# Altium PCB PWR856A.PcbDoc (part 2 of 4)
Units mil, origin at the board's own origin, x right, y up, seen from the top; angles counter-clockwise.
Board outline 4000 x 4000 mil, 8 copper layers (Top Layer, Signal Layer 1, Signal Layer 2, Signal Layer 3, Signal Layer 4, Signal Layer 5, Signal Layer 6, Bottom Layer), stack 60.4 mil thick; 246 components, 78 nets, 563 pads, 817 vias.
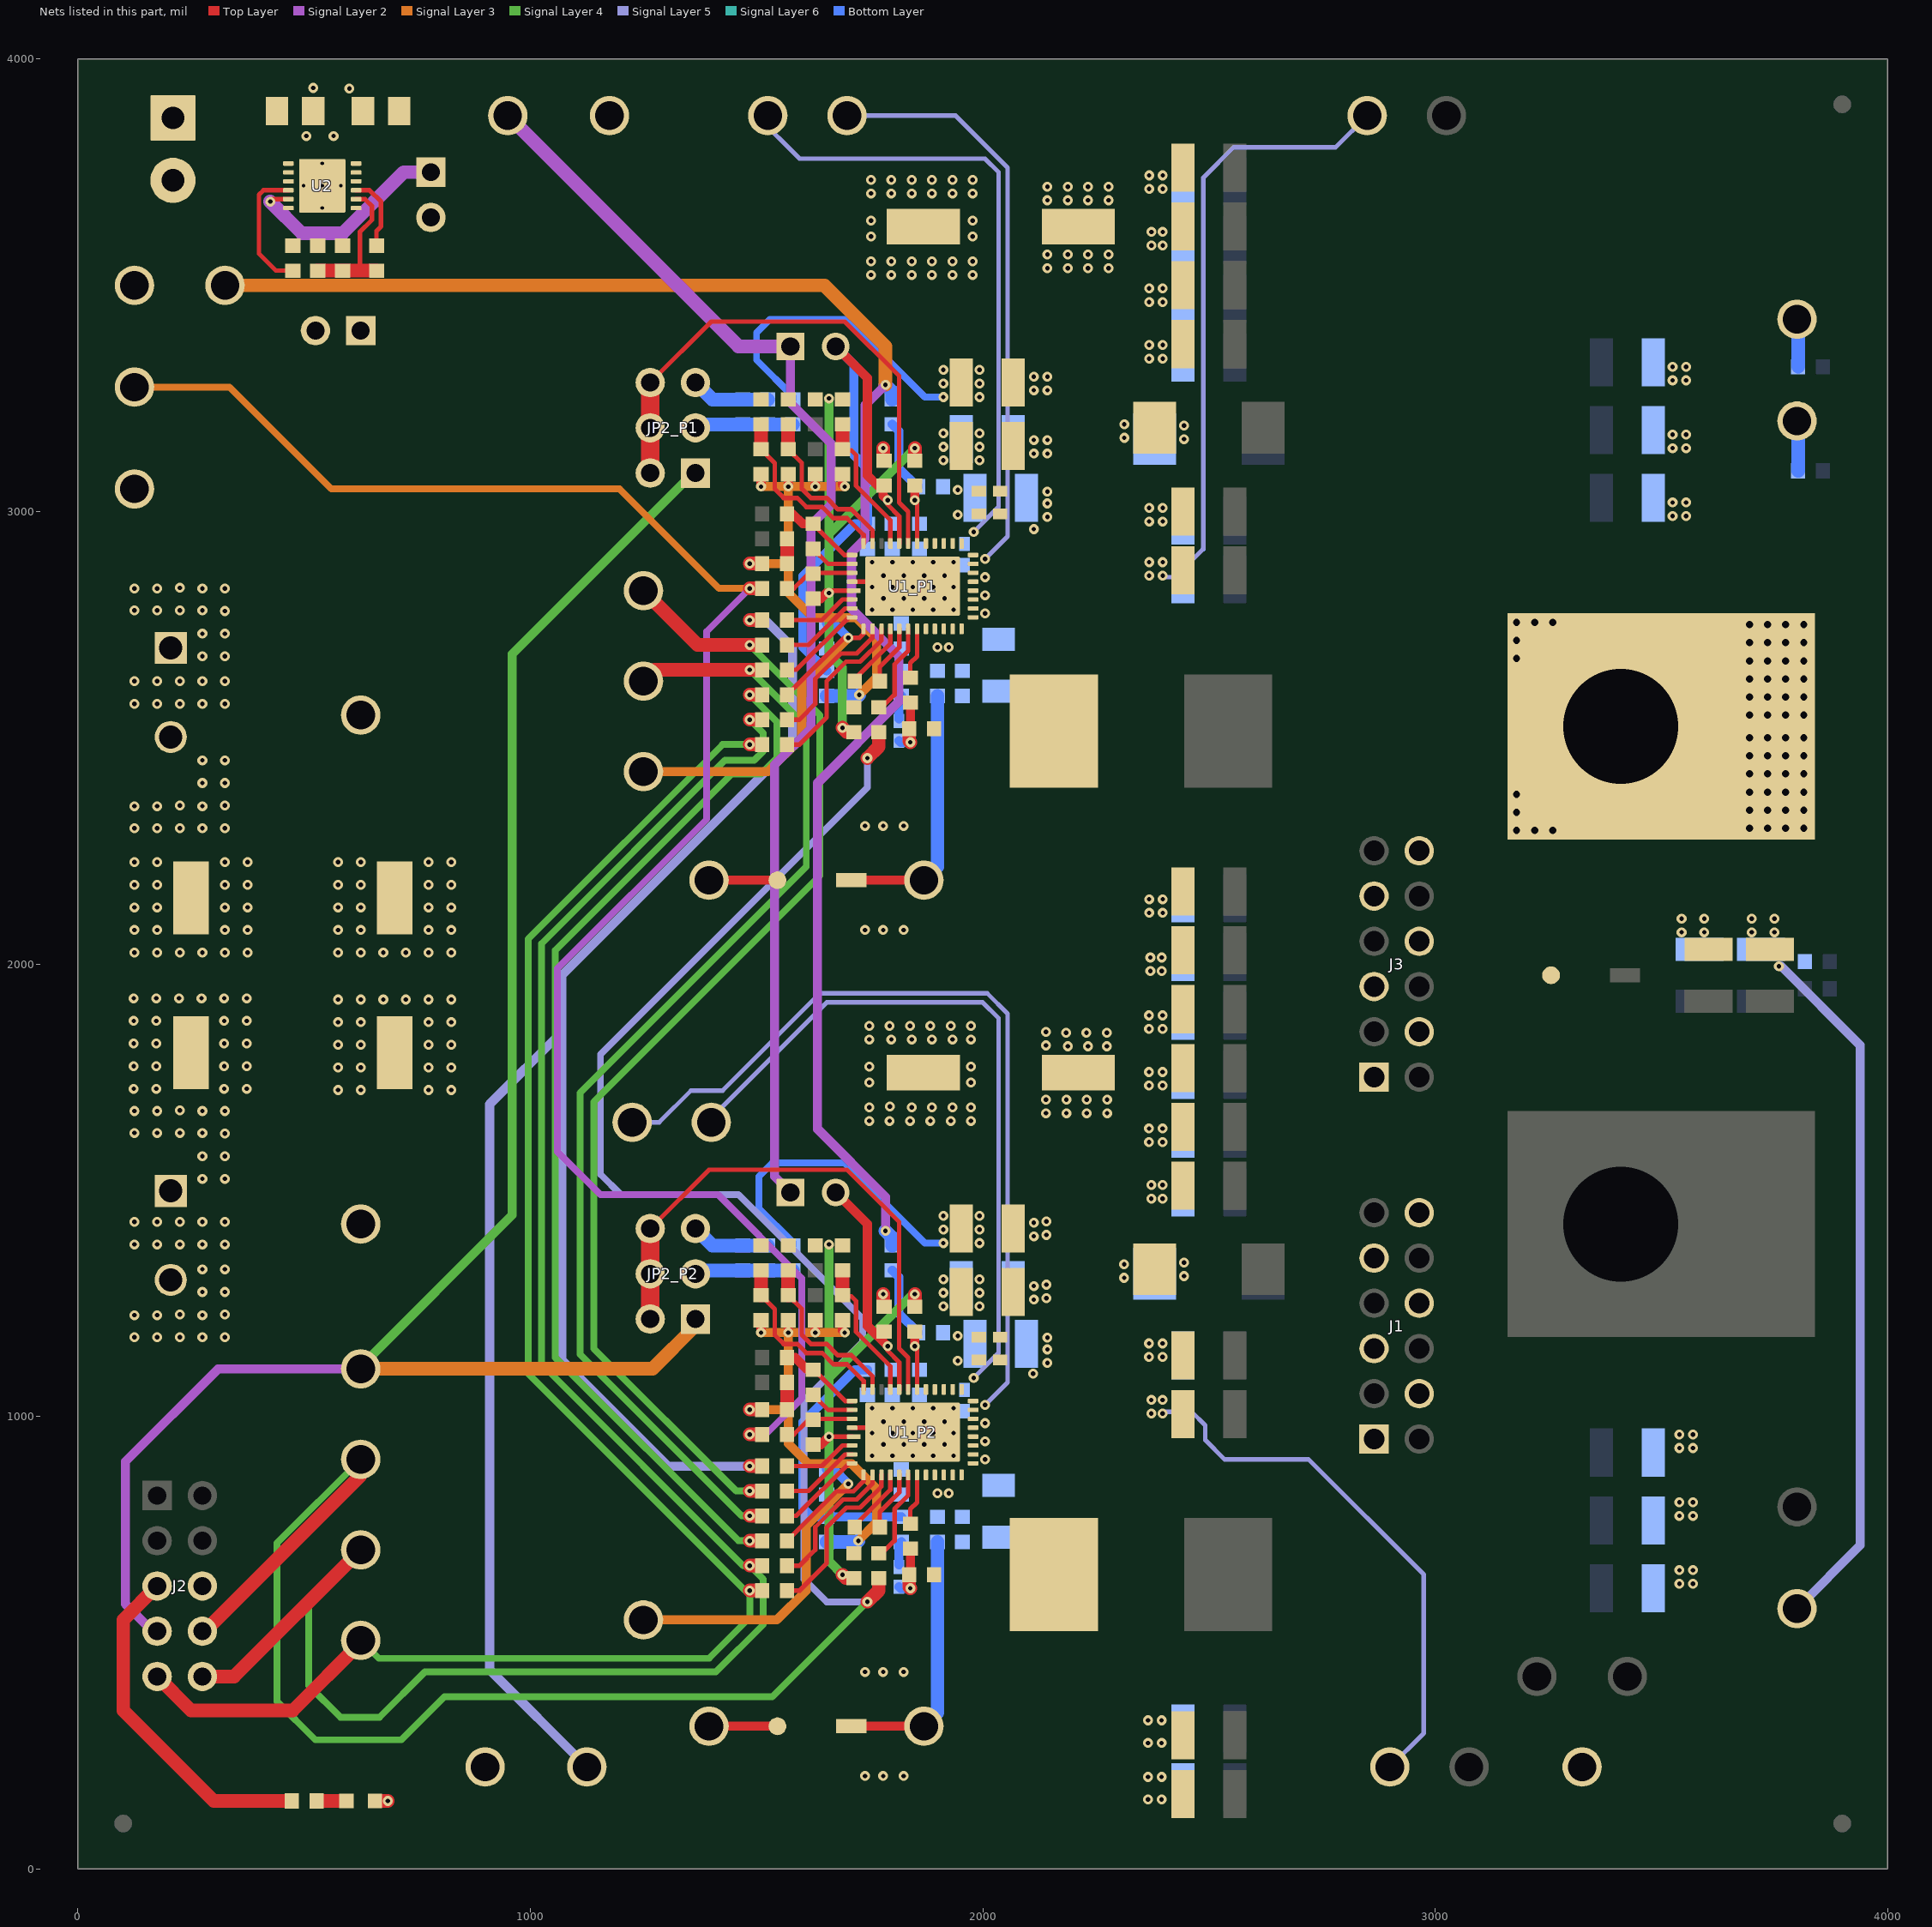
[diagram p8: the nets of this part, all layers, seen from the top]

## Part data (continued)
C47 C48 C63 C64: library part CMP-0012642-3, "CAP, Tantalum Polymer, 470 uF, 6.3 V, +/- 20%, 0.01 ohm, 7343-40 SMD", Cap_Case=D4, Manufacturer=Panasonic, PartNumber=6TPF470MAH, Supplier Part Number 1=P16636CT-ND, Tolerance_%=20%, Value1="0.01 ohm", Value2=6.3V, ValueDisplayed=470uF
D1_P1 D1_P2: library part CMP-0028846-2, "Diode, Schottky, 30 V, 0.5 A, SOD-523", Manufacturer="Torex USA Corporation", PartNumber=XBS053V15R-G, Supplier Part Number 1=XBS053V15R-G-ND, Value1=0.5A, Value2=0.47V
FID1 FID2 FID3 FID4 FID5 FID6: library part CMP-0077181-1, "Fiducial mark.  There is nothing to buy or mount.", Manufacturer=N/A
H3 H4 H5 H6: library part CMP-0003620-1, "Bumpon, Hemisphere, 0.44 X 0.20, Clear", Manufacturer=3M, PartNumber="SJ-5303 (CLEAR)", Supplier Part Number 1=SJ5303-7-ND
J1 J3: library part CMP-0055669-1, "Receptacle, 2.54mm, 6x2, Gold, TH", Color=Black, Current_A=5.7A, Manufacturer=Samtec, PartNumber=SSW-106-23-F-D, Voltage_V=550V
J2: library part CMP-0054834-1, "Header (shrouded), 100mil, 5x2, Gold, TH", Manufacturer="TE Connectivity", PartNumber=5103308-1, Supplier Part Number 1=A33159-ND
JP1_P1 JP1_P2: library part CMP-0054576-1, "Header, 2.54 mm, 2x1, Gold, TH", Manufacturer="Sullins Connector Solutions", PartNumber=GBC02SAAN
JP2_P1 JP2_P2: library part CMP-0054565-1, "Header, 100mil, 3x2, Gold, TH", Color=Black, Current_A=3A, Manufacturer="Sullins Connector Solutions", PartNumber=PBC03DAAN, Supplier Part Number 1=S2011E-03-ND, Voltage_V=1.8kV
JP3 JP4: library part CMP-0054952-1, "Header, 100mil, 2x1, Tin, TH", Manufacturer="TE Connectivity", PartNumber=5-146278-2, Supplier Part Number 1=5-146278-2-ND
L1 L2: library part CMP-0060889-1, "Inductor, Shielded, Ferrite, 300 nH, 52 A, 0.00015 ohm, SMD", Manufacturer=Coilcraft, PartNumber=SLC1480-301MLB, Value1="0.00015 ohm", Value2=52A, ValueDisplayed=300nH
LBL1: library part CMP-0003625-1, "Thermal Transfer Printable Labels, 0.650\" W x 0.200\" H - 10,000 per roll", Manufacturer=Brady, PartNumber=THT-14-423-10, Supplier Part Number 1=97C5133
LED1: library part CMP-0002905-1, "LED, Green, SMD", Color=Green, Manufacturer="Wurth Elektronik", PartNumber=150060GS75000, Supplier Part Number 1=732-4971-1-ND, Value1=W, Value2=3.2V
Logo1: library part CMP-0074837-1, "IEC 61010-1 Hot Surface Warning"
Logo4: library part CMP-0074769-1
Logo5: library part CMP-0074847-1, "FCC_disclaimer"
NT1_P1 NT1_P2: library part CMP-0078142-1, "Single point connection between nets.", Manufacturer=N/A
R1_P1 R1_P2 R2_P1 R2_P2 R4_P1 R4_P2 R15_P1 R15_P2 R16_P1 R16_P2 R17_P1 R17_P2 R19_P1 R19_P2 R22_P1 R22_P2 R23_P1 R23_P2 R24_P1 R24_P2 R25_P1 R25_P2 R27_P1 R27_P2 R32 R33 R37 R39: library part CMP-0025874-3, "RES, 0, 5%, 0.1 W, 0603", Manufacturer=Panasonic, PartNumber=ERJ-3GEY0R00V, Power_W=100mW, Supplier Part Number 1=P0.0GCT-ND, TempCo="600 ppm/C", Tolerance_%=5%, Value2=0.1W, Value_Code=0000, ValueDisplayed=0
R3_P1 R3_P2: library part CMP-0025703-4, "RES, 10, 5%, 0.1 W, AEC-Q200 Grade 0, 0603", Manufacturer=Vishay-Dale, Power_W=100mW, Supplier Part Number 1=541-10GCT-ND, TempCo="200 ppm/C", Tolerance_%=5%, Value2=0.1W, Value_Code=10R0, ValueDisplayed=10
R5_P1 R5_P2 R34 R35 R36 R38: library part CMP-0022448-4, "RES, 49.9, 1%, 0.1 W, AEC-Q200 Grade 0, 0603", Manufacturer=Vishay-Dale, PartNumber=CRCW060349R9FKEA, Power_W=100mW, Supplier Part Number 1=541-49.9HCT-ND, TempCo="100 ppm/C", Tolerance_%=1%, Value2=0.1W, Value_Code=49R9, ValueDisplayed=49.9
R6_P1 R6_P2: library part CMP-0018617-3, "RES, 1.0, 5%, 0.25 W, AEC-Q200 Grade 0, 1206", Manufacturer=Vishay-Dale, PartNumber=CRCW12061R00JNEA, Power_W=250mW, Supplier Part Number 1=541-1.0ECT-ND, TempCo="200 ppm/C", Tolerance_%=5%, Value2=0.25W, Value_Code=1R00, ValueDisplayed=1.0
R7_P1 R7_P2: library part CMP-0023197-3, "RES, 5.11 k, 1%, 0.1 W, 0603", Manufacturer="Yageo America", Power_W=100mW, Supplier Part Number 1=311-5.11KHRCT-ND, TempCo="200 ppm/C", Tolerance_%=1%, Value2=0.1W, Value_Code=5k11, ValueDisplayed=5.11k
R8_P1 R8_P2 R26_P1 R26_P2: library part CMP-0022746-3, "RES, 10.0 k, 1%, 0.1 W, 0603", Manufacturer="Yageo America", PartNumber=RC0603FR-0710KL, Power_W=100mW, Supplier Part Number 1=311-10.0KHRCT-ND, TempCo="200 ppm/C", Tolerance_%=1%, Value2=0.1W, Value_Code=10k0, ValueDisplayed=10.0k
R9_P1 R9_P2: library part CMP-0023018-3, "RES, 30.1 k, 1%, 0.1 W, 0603", Manufacturer="Yageo America", Power_W=100mW, Supplier Part Number 1=311-30.1KHRCT-ND, TempCo="200 ppm/C", Tolerance_%=1%, Value2=0.1W, Value_Code=30k1, ValueDisplayed=30.1k
R10_P1 R10_P2 R11_P1 R11_P2 R12_P1 R12_P2 R18_P1 R18_P2 R20_P1 R20_P2: library part CMP-0022000-4, "RES, 10.5 k, 1%, 0.1 W, AEC-Q200 Grade 0, 0603", Manufacturer=Vishay-Dale, PartNumber=CRCW060310K5FKEA, Power_W=100mW, Supplier Part Number 1=541-10.5KHCT-ND, TempCo="100 ppm/C", Tolerance_%=1%, Value2=0.1W, Value_Code=10k5, ValueDisplayed=10.5k
R13_P1 R13_P2: library part CMP-0022490-4, "RES, 53.6 k, 1%, 0.1 W, AEC-Q200 Grade 0, 0603", Manufacturer=Vishay-Dale, PartNumber=CRCW060353K6FKEA, Power_W=100mW, Supplier Part Number 1=541-53.6KHCT-ND, TempCo="100 ppm/C", Tolerance_%=1%, Value2=0.1W, Value_Code=53k6, ValueDisplayed=53.6k
R14_P1 R14_P2: library part CMP-0022708-3, "RES, 7.50 k, 1%, 0.1 W, 0603", Manufacturer=Panasonic, Power_W=100mW, Supplier Part Number 1=P7.50KHCT-ND, TempCo="100 ppm/C", Tolerance_%=1%, Value2=0.1W, Value_Code=7k50, ValueDisplayed=7.50k
R21_P1 R21_P2: library part CMP-0022237-4, "RES, 24.9 k, 1%, 0.1 W, AEC-Q200 Grade 0, 0603", Manufacturer=Vishay-Dale, PartNumber=CRCW060324K9FKEA, Power_W=100mW, Supplier Part Number 1=541-24.9KHCT-ND, TempCo="100 ppm/C", Tolerance_%=1%, Value2=0.1W, Value_Code=24k9, ValueDisplayed=24.9k
R28: library part CMP-0022109-5, "RES, 1.00 k, 1%, 0.1 W, AEC-Q200 Grade 0, 0603", Manufacturer=Vishay-Dale, PartNumber=CRCW06031K00FKEA, Power_W=100mW, Supplier Part Number 1=541-1.00KHCT-ND, TempCo="100 ppm/C", Tolerance_%=1%, Value2=0.1W, Value_Code=1k00, ValueDisplayed=1.00k
R29: library part CMP-0022439-4, "RES, 47.5 k, 1%, 0.1 W, AEC-Q200 Grade 0, 0603", Manufacturer=Vishay-Dale, PartNumber=CRCW060347K5FKEA, Power_W=100mW, Supplier Part Number 1=541-47.5KHCT-ND, TempCo="100 ppm/C", Tolerance_%=1%, Value2=0.1W, Value_Code=47k5, ValueDisplayed=47.5k
R30: library part CMP-0022066-4, "RES, 15.0 k, 1%, 0.1 W, AEC-Q200 Grade 0, 0603", Manufacturer=Vishay-Dale, PartNumber=CRCW060315K0FKEA, Power_W=100mW, Supplier Part Number 1=541-15.0KHCT-ND, TempCo="100 ppm/C", Tolerance_%=1%, Value2=0.1W, Value_Code=15k0, ValueDisplayed=15.0k
R31: library part CMP-0023182-2, "RES, 560 k, 1%, 0.1 W, 0603", Manufacturer="Yageo America", PartNumber=RC0603FR-07560KL, Power_W=100mW, Supplier Part Number 1=311-560KHRCT-ND, TempCo="200 ppm/C", Tolerance_%=1%, Value2=0.1W, Value_Code=560k
SH-JP1 SH-JP2 SH-JP3 SH-JP4: "Shunt, 100mil, Gold plated, Black", Alternate Manufacturer=Samtec, Alternate PartNumber=SNT-100-BK-G, Manufacturer=3M, Supplier Part Number 1=3M9580-ND
SMB1_P1 SMB1_P2 SMB2: library part CMP-0075106-1, "Connector, Receptacle, 50 ohm, TH", Manufacturer="JAE Electronics", PartNumber=SMBR004D00, Supplier Part Number 1=SMBR004D00-ND
T1 T2: library part CMP-0055506-1, "Terminal Block, 2x1, 5mm, Green, TH", Color=Green, Manufacturer="Phoenix Contact", Supplier Part Number 1=277-6405-ND
T3 T5: library part CMP-0055443-1, "Terminal 90A Lug", Manufacturer=Panduit, Supplier Part Number 1=CB70-14-CY-ND, Voltage_V=600V
T4: library part CMP-0074913-1, "Terminal Block, 3.5mm Pitch, 2x1, TH", Color=Grey, Current_A=6A, Manufacturer="On-Shore Technology", PartNumber=ED555/2DS, Supplier Part Number 1=ED1514-ND, Voltage_V=150V
TP1_P1 TP1_P2 TP6 TP12 TP13 TP19 TP26: library part CMP-0055147-1, "Test Point, Multipurpose, Red, TH", Color=Red, Manufacturer=Keystone, Supplier Part Number 1=36-5010-ND
TP2_P1 TP2_P2 TP5_P1 TP5_P2 TP7 TP8 TP9 TP10 TP17 TP18 TP21 TP27 TP29 TP31: library part CMP-0055149-1, "Test Point, Multipurpose, White, TH", Color=White, Manufacturer=Keystone, Supplier Part Number 1=36-5012-ND
TP3_P1 TP3_P2 TP4_P1 TP4_P2 TP11 TP15 TP16 TP20 TP23 TP24 TP25 TP30 TP32: library part CMP-0055148-1, "Test Point, Multipurpose, Black, TH", Color=Black, Manufacturer=Keystone, Supplier Part Number 1=36-5011-ND
TP14 TP28: library part CMP-0055149-1, "Test Point, Multipurpose, White, TH", Color=White, Manufacturer=Keystone, PartNumber=5012, Supplier Part Number 1=36-5012-ND
TP22: library part CMP-0055147-1, "Test Point, Multipurpose, Red, TH", Color=Red, Manufacturer=Keystone, PartNumber=5010, Supplier Part Number 1=36-5010-ND
U1_P1 U1_P2: library part CMP-0014071-6, "2.95-16V 40A PMBUS Stackable Synchronous Buck Converter, RVF0040A (LQFN-CLIP-40)", Alternate Manufacturer="Texas Instruments", Alternate PartNumber=TPS546D24RVFT
U2: library part CMP-0066007-2, "800-mA Ultra-Low-Noise, High-PSRR LDO, DNT0012B (WSON-12)", Alternate Manufacturer="Texas Instruments", PartNumber=LP38798SD-ADJ/NOPB
ZZ1: library part CMP-0003616-3
ZZ2: library part CMP-0077236-1
ZZ3: library part CMP-0077237-1
ZZ4: library part CMP-0077238-1
ZZ5: library part AssemblyNote, "This Assembly Note will show in the PcbDoc and associated outputs"

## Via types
v1: diameter 22, hole 10, Top Layer to Bottom Layer, tented both sides, 676 vias
v2: diameter 32, hole 16, Top Layer to Bottom Layer, 116 vias
v3: diameter 22, hole 10, Top Layer to Bottom Layer, tented bottom, 20 vias
v4: diameter 19.68, hole 7.87, Top Layer to Bottom Layer, 5 vias

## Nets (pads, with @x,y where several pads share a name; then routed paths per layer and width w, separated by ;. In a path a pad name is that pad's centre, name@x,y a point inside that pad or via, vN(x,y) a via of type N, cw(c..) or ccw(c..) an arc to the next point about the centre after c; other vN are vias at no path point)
ADRSEL_P1: R12_P1.2 R20_P1.1 U1_P1.31 | length 378.2
  Top Layer w10: R12_P1.2@1570,3137.56 1600,3107.56 1600,3050 1620,3030 1655,3030 1680,3005 1710,3005 1756.42,2958.58 U1_P1.31@1756.42,2929.49
  Top Layer w30: R12_P1.2@1570,3137.56 R20_P1.1@1570,3192.44
ADRSEL_P2: R12_P2.2 R20_P2.1 U1_P2.31 | length 378.2
  Top Layer w10: R12_P2.2@1570,1267.56 1600,1237.56 1600,1180 1620,1160 1655,1160 1680,1135 1710,1135 1756.42,1088.58 U1_P2.31@1756.42,1059.49
  Top Layer w30: R12_P2.2@1570,1267.56 R20_P2.1@1570,1322.44
AGND_P1: C11_P1.1 C18_P1.2 C21_P1.2 NT1_P1.1 R18_P1.2 R19_P1.2 R20_P1.2 R21_P1.2 U1_P1.37 | length 1149.7
  Top Layer w10: v1@1662.16,2825.16 U1_P1.37@1711.14,2825.16
  Top Layer w20: C21_P1.2@1625,2807.44 1642.44,2807.44 v1@1655,2820
  Top Layer w30: v1(1690,2522) 1699.56,2512.44 C18_P1.2@1715,2512.44 ; C11_P1.1@1850,3112.56 v1(1850,3140)
  Signal Layer 4 w20: v1(1660,3250) 1660,2950 ; v1(1690,2522) 1690,2655 1660,2685 v1(1660,2820) 1660,2950 ; v1(1850,3140) 1660,2950
AGND_P2: C11_P2.1 C18_P2.2 C21_P2.2 NT1_P2.1 R18_P2.2 R19_P2.2 R20_P2.2 R21_P2.2 U1_P2.37 | length 1148.8
  Top Layer w10: v1@1662.16,955.16 U1_P2.37@1711.14,955.16
  Top Layer w20: C21_P2.2@1625,937.44 1642.44,937.44 v1@1655,950
  Top Layer w30: v1(1690,650) 1697.56,642.44 C18_P2.2@1715,642.44 ; C11_P2.1@1850,1242.56 v1(1850,1270)
  Signal Layer 4 w20: v1(1660,1380) 1660,1085 ; v1(1690,650) 1660,680 v1(1660,955) 1660,1085 ; v1(1850,1270) 1845,1270 1660,1085
AUX_5V: C23.1 JP1_P1.1 JP1_P2.1 TP6.1 U2.10 U2.11 U2.12 | length 2809.8
  Signal Layer 2 w20: JP1_P2.1@1575,1495 1540,1530 1540,2440 1620,2520 1620,2970 1665,3015 1665,3150 1575,3240 JP1_P1.1@1575,3365
  Signal Layer 2 w30: TP6.1@950,3875 1460,3365 JP1_P1.1@1575,3365
AVIN: C22.1 JP4.2 R2_P1.2 R2_P2.2 T4.1 TP19.1 U2.1 U2.2 U2.3 | length 3759.5
  Signal Layer 2 w20: v1(1785,1410) 1785,1485 1635,1635 1635,2400 1815,2580 1815,2680 1710,2785 1710,2909.46 1740,2939.46 1740,3235 v1(1785,3280)
  Signal Layer 3 w30: TP19.1@325,3500 1650,3500 1785,3365 v1(1785,3280)
  Bottom Layer w30: v1(1785,1410) 1800,1395 R2_P2.2@1800,1377.56 ; v1(1785,3280) 1800,3265 R2_P1.2@1800,3247.56
AVIN_P1: C10_P1.2 C11_P1.2 R2_P1.1 R3_P1.1 U1_P1.26 | length 292.6
  Top Layer w10: v1(1850,3025) 1854.84,3020.16 U1_P1.26@1854.84,2929.49
  Top Layer w20: v1(1850,3025) C11_P1.2@1850,3057.44
  Bottom Layer w20: R2_P1.1@1800,3192.44 1815,3177.44 1815,3095 1855,3055 R3_P1.1@1857.44,3055
AVIN_P2: C10_P2.2 C11_P2.2 R2_P2.1 R3_P2.1 U1_P2.26 | length 291.2
  Top Layer w10: v1(1850,1155) 1854.84,1150.16 U1_P2.26@1854.84,1059.49
  Top Layer w20: v1(1850,1155) C11_P2.2@1850,1187.44
  Bottom Layer w20: R2_P2.1@1800,1322.44 1815,1307.44 1815,1227.44 R3_P2.1@1857.44,1185
BP1V5_P1: C18_P1.1 C19_P1.1 R7_P1.2 R8_P1.1 R10_P1.1 R11_P1.1 R12_P1.1 R13_P1.1 U1_P1.4 | length 1237.5
  Top Layer w10: C19_P1.1@1717.44,2630 1795.79,2708.35 U1_P1.4@1795.79,2740.51
  Top Layer w20: v1(1510,3055) R13_P1.1@1510,3082.44 ; v1(1570,3055) R12_P1.1@1570,3082.44 ; v1(1630,3055) R11_P1.1@1630,3082.44 ; R10_P1.1@1690,3082.44 1690,3060 v1(1695,3055)
  Top Layer w30: v1(1485,2885) R8_P1.1@1512.44,2885
  Signal Layer 3 w20: v1(1485,2885) 1570,2885 ; v1(1510,3055) v1(1570,3055) ; v1(1695,3055) v1(1630,3055) v1(1570,3055) ; v1(1727,2595) 1765,2633 1765,2720 1720,2765 1625,2765 1570,2820 1570,2885 ; 1570,2885 v1(1570,3055)
  Bottom Layer w30: R7_P1.2@1655,2592.44 1724.44,2592.44 v1(1727,2595)
BP1V5_P2: C18_P2.1 C19_P2.1 R7_P2.2 R8_P2.1 R10_P2.1 R11_P2.1 R12_P2.1 R13_P2.1 U1_P2.4 | length 1241.3
  Top Layer w10: C19_P2.1@1717.44,755 1717.44,759.44 1795.79,837.79 U1_P2.4@1795.79,870.51
  Top Layer w20: v1(1510,1185) R13_P2.1@1510,1212.44 ; v1(1570,1185) R12_P2.1@1570,1212.44 ; v1(1630,1185) R11_P2.1@1630,1212.44 ; R10_P2.1@1690,1212.44 1690,1190 v1(1695,1185)
  Top Layer w30: v1(1485,1015) R8_P2.1@1512.44,1015
  Signal Layer 3 w20: v1(1485,1015) 1570,1015 ; v1(1510,1185) v1(1570,1185) ; v1(1695,1185) v1(1630,1185) v1(1570,1185) ; v1(1725,725) 1765,765 1765,840 1710,895 1615,895 1570,940 1570,1015 ; 1570,1015 v1(1570,1185)
  Bottom Layer w30: R7_P2.2@1655,722.44 1722.44,722.44 v1(1725,725)
CLK: J2.9 R25_P1.2 R25_P2.2 TP10.1 | length 3893.9
  Top Layer w30: J2.9@175,425 250,350 475,350 625,500 TP10.1@625,505 ; v1(1485,615) R25_P2.2@1512.44,615 ; v1(1485,2485) R25_P1.2@1512.44,2485
  Signal Layer 4 w15: TP10.1@625,505 665,465 1395,465 1485,555 v1(1485,615) 1475,615 995,1095 995,2055 1425,2485 v1(1485,2485)
CNTL: J2.7 JP2_P1.1 JP2_P2.1 TP9.1 | length 4098.6
  Signal Layer 2 w20: J2.7@175,525 165,525 105,585 105,900 310,1105 TP9.1@625,1105
  Signal Layer 4 w20: TP9.1@625,1105 625,1110 960,1445 960,2685 1360,3085 JP2_P1.1@1365,3085
  Signal Layer 3 w30: TP9.1@625,1105 1270,1105 1365,1200 JP2_P2.1@1365,1215
DATA: J2.10 R23_P1.2 R23_P2.2 TP7.1 | length 4452.6
  Top Layer w30: J2.10@275,425 345,425 TP7.1@625,705 ; v1(1485,670) R23_P2.2@1512.44,670 ; v1(1485,2540) R23_P1.2@1512.44,2540
  Signal Layer 4 w15: TP7.1@625,705 510,590 510,405 580,335 666.93,335 766.93,435 1410,435 1515,540 1515,640 v1(1485,670) 1470,670 1025,1115 1025,2045 1430,2450 1495,2450 1515,2470 1515,2510 v1(1485,2540)
DGND_P1: C19_P1.2 U1_P1.5 | length 128.3
  Top Layer w10: C19_P1.2@1772.56,2630 1772.56,2656.56 1815.47,2699.47 U1_P1.5@1815.47,2740.51
DGND_P2: C19_P2.2 U1_P2.5 | length 133.3
  Top Layer w10: C19_P2.2@1772.56,755 1772.56,788.56 1815.47,831.47 U1_P2.5@1815.47,870.51
EN_P1: JP2_P1.2 JP2_P1.4 JP2_P1.6 U1_P1.27 | length 1234.5
  Top Layer w10: JP2_P1.6@1265,3285 1400,3420 1695,3420 1815,3300 1815,3020 1835.16,2999.84 U1_P1.27@1835.16,2929.49
  Top Layer w40: JP2_P1.2@1265,3085 JP2_P1.4@1265,3185 JP2_P1.6@1265,3285
EN_P2: JP2_P2.2 JP2_P2.4 JP2_P2.6 U1_P2.27 | length 1230.3
  Top Layer w10: JP2_P2.6@1265,1415 1395,1545 1700,1545 1815,1430 1815,1150 1835.16,1129.84 U1_P2.27@1835.16,1059.49
  Top Layer w40: JP2_P2.2@1265,1215 JP2_P2.4@1265,1315 JP2_P2.6@1265,1415
EXT_SYNC: R17_P1.1 R17_P2.1 TP27.1 | length 4253.7
  Top Layer w30: v1(1485,890) R17_P2.1@1512.44,890 ; v1(1485,2760) R17_P1.1@1512.44,2760
  Signal Layer 5 w20: TP27.1@1125,225 910,440 910,1690 1070,1850 ; v1(1485,890) 1305,890 1070,1125 1070,1850 ; v1(1485,2760) 1520,2760 1580,2700 1580,2485 1070,1975 1070,1850
GND_P1: C1_P1.1 C1_P2.1 C2_P1.2 C2_P2.2 C3_P1.2 C3_P2.2 C4_P1.2 C4_P2.2 C5_P1.1 C5_P2.1 C6_P1.1 C6_P2.1 C7_P1.1 C7_P2.1 C8_P1.1 C8_P2.1 C9_P1.1 C9_P2.1 C10_P1.1 C10_P2.1 C14_P1.1 C14_P2.1 C15_P1.1 C15_P2.1 C16_P1.1 C16_P2.1 C20_P1.2 C20_P2.2 C22.2 C23.2 C24.2 C25.2 C26.2 C27.2 C28.2 C29.2 C30.2 C31.2 C32.2 C33.2 C34.2 C35.1 C36.1 C37.1 C38.1 C39.1 C40.1 C41.1 C42.1 C43.1 C44.1 C45.1 C46.1 C47.2 C48.2 C49.1 C50.1 C51.1 C52.1 C53.1 C54.1 C55.1 C56.1 C57.1 C58.1 C59.1 C60.1 C61.1 C62.1 C63.2 C64.2 C65.2 C66.2 C67.2 C68.2 C69.2 C70.2 C71.2 C72.2 J1.1 J1.4 J1.5 J1.8 J1.9 J1.12 J2.6 J3.1 J3.4 J3.5 J3.8 J3.9 J3.12 JP2_P1.5 JP2_P2.5 JP3.2 LED1.1 NT1_P1.2 NT1_P2.2 R6_P1.1 R6_P2.1 R14_P1.2 R14_P2.2 R30.1 R31.1 R36.1 SMB1_P1.2 SMB1_P2.2 SMB2.2 T2.1 T2.2 T4.2 T5.1 TP3_P1.1 TP3_P2.1 TP4_P1.1 TP4_P2.1 TP11.1 TP15.1 TP16.1 TP20.1 TP23.1 TP24.1 TP25.1 TP30.1 TP32.1 U1_P1.13 U1_P1.14 U1_P1.15 U1_P1.16 U1_P1.17 U1_P1.18 U1_P1.19 U1_P1.20 U1_P1.36 U1_P1.41@1845,2835 U1_P2.13 U1_P2.14 U1_P2.15 U1_P2.16 U1_P2.17 U1_P2.18 U1_P2.19 U1_P2.20 U1_P2.36 U1_P2.41@1845,965 U2.6 U2.7 U2.13 | length 8256.8
  Top Layer w10: U1_P2.36@1711.14,974.84 1835.16,974.84 U1_P2.41@1845,965 ; U1_P1.36@1711.14,2844.84 1835.16,2844.84 U1_P1.41@1845,2835
  Top Layer w20: TP4_P2.1@1397.48,315 SMB1_P2.2@1546.26,315 ; TP4_P1.1@1397.48,2185 SMB1_P1.2@1546.26,2185
  Top Layer w30: LED1.1@656.5,150 v1(685,150) ; C15_P2.1@1780,1242.56 v1(1780,1270) ; C15_P1.1@1780,3112.56 v1(1780,3140)
  Signal Layer 5 w10: TP3_P2.1@1225,1650 1285,1650 1355,1720 1425,1720 1640,1935 2010,1935 2055,1890 2055,1075 v1(2005,1025) ; TP3_P1.1@1700,3875 1940,3875 2055,3760 2055,2945 v1(2005,2895) ; v1@2400,1010 2462.13,1010 2492,980.13 2492,947.72 2534.8,904.92 2720.08,904.92 2975,650 2975,300 TP30.1@2900,225 ; v1@2400,2855 2425,2855 2486.8,2916.8 ; 2487.81,2916.8 2487.81,3738.09 2554.72,3805 2780,3805 TP16.1@2850,3875
  Signal Layer 5 w20: v1(3760,1995) 3765,1995 3940,1820 3940,715 TP25.1@3800,575
  Signal Layer 6 w10: 2486.8,2916.8 2487.81,2916.8
  Bottom Layer w30: JP2_P2.5@1365,1415 1402.44,1377.56 R14_P2.2@1470,1377.56 C20_P2.2@1525,1377.56 ; JP2_P1.5@1365,3285 1402.44,3247.56 R14_P1.2@1470,3247.56 C20_P1.2@1525,3247.56
  other v1: 2365.4,153 2395.4,153 2365.4,203 2395.4,203 1740,205 1780,205 1825,205 2365.4,278 2395.4,278 2365.4,328 2395.4,328 1740,435 1780,435 1825,435 3540,630 3570,630 3540,660 3570,660 3540,780 3570,780 3540,810 3570,810 2005,905 1845.48,913 1890.48,913 1935.48,913 3540,930 3570,930 1870.48,938 1915.48,938 2005,945 3540,960 3570,960 1845.48,963 1890.48,963 1935.48,963 2005,985 1870.48,988 1915.48,988 2372.59,1006.2 2397.59,1006.2 1845.48,1018 1890.48,1018 1935.48,1018 2372.59,1036.2 2397.59,1036.2 2111.59,1094.2 2142.92,1118 2367.59,1131.2 2397.59,1131.2 2142.92,1148 2367.59,1161.2 2397.59,1161.2 2142.92,1174 125,1175 175,1175 225,1175 275,1175 325,1175 125,1223.62 175,1223.62 275,1223.62 225,1225 325,1225 2112.92,1258 2140.84,1261 275,1275 325,1275 2112.92,1288 2140.84,1291 2312.59,1306.2 2445,1310 275,1325 325,1325 2312.59,1336.2 2445,1340 125,1380 175,1380 225,1380 275,1380 325,1380 2112.92,1398 2140.84,1401 2112.92,1428 125,1430 175,1430 225,1430 275,1430 325,1430 2140.84,1431 2372.59,1481.2 2397.59,1481.2 2372.59,1511.2 2397.59,1511.2 275,1525 325,1525 275,1575 325,1575 2367.59,1606.2 2397.59,1606.2 325,1625 125,1626.38 175,1626.38 225,1626.38 275,1626.38 2367.59,1636.2 2397.59,1636.2 2140,1670 2185,1670 2230,1670 2275,1670 125,1675 175,1675 275,1675 325,1675 225,1676.38 2140,1700 2185,1700 2230,1700 2275,1700 575,1721.26 625,1721.26 775,1721.26 825,1721.26 123.2,1724.07 173.2,1724.07 323.2,1724.07 373.2,1724.07 2367.59,1731.2 2397.59,1731.2 2367.59,1761.2 2397.59,1761.2 575,1771.26 625,1771.26 775,1771.26 825,1771.26 123.2,1774.07 173.2,1774.07 323.2,1774.07 373.2,1774.07 2187.92,1818 2232.92,1818 2274.18,1818 2140,1820 575,1821.26 625,1821.26 775,1821.26 825,1821.26 123.2,1824.07 173.2,1824.07 323.2,1824.07 373.2,1824.07 2184.18,1848 2229.18,1848 2274.18,1848 2140,1850 2367.59,1856.2 2397.59,1856.2 575,1871.26 625,1871.26 775,1871.26 825,1871.26 123.2,1874.07 173.2,1874.07 323.2,1874.07 373.2,1874.07 2367.59,1886.2 2397.59,1886.2 575,1921.26 625,1921.26 675,1921.26 725,1921.26 775,1921.26 825,1921.26 123.2,1924.07 173.2,1924.07 223.2,1924.07 273.2,1924.07 323.2,1924.07 373.2,1924.07 2370.51,1984.2 2395.51,1984.2 2370.51,2014.2 2395.51,2014.2 3545,2070 3595,2070 3700,2070 3750,2070 1740,2075 1780,2075 1825,2075 3545,2100 3595,2100 3700,2100 3750,2100 2367.92,2113 2397.92,2113 2367.92,2143 2397.92,2143 1740,2305 1780,2305 1825,2305 2005,2775 1845.48,2783 1890.48,2783 1935.48,2783 1870.48,2808 1915.48,2808 2005,2815 1845.48,2833 1890.48,2833 1935.48,2833 2005,2855 1870.48,2858 1915.48,2858 2367.92,2858 2397.92,2858 1845.48,2888 1890.48,2888 1935.48,2888 2367.92,2888 2397.92,2888 2112.92,2961 2367.92,2978 2397.92,2978 2142.92,2988 3525,2990 3555,2990 2367.92,3008 2397.92,3008 2142.92,3018 3525,3020 3555,3020 2142.92,3044 2112.92,3128 2142.92,3128 3525,3140 3555,3140 2112.92,3158 2142.92,3158 2445,3160 2312.92,3163 3525,3170 3555,3170 2445,3190 2312.92,3193 2112.92,3268 2142.92,3268 3525,3290 3555,3290 2112.92,3298 2142.92,3298 3525,3320 3555,3320 2367.92,3338 2397.92,3338 2367.92,3368 2397.92,3368 2367.92,3463 2397.92,3463 2367.92,3493 2397.92,3493 2142.92,3538 2187.92,3538 2232.92,3538 2277.92,3538 2142.92,3568 2187.92,3568 2232.92,3568 2277.92,3568 2372.92,3588 2397.92,3588 2372.92,3618 2397.92,3618 2142.92,3688 2187.92,3688 2232.92,3688 2277.92,3688 2367.92,3713 2397.92,3713 2142.92,3718 2187.92,3718 2232.92,3718 2277.92,3718 2367.92,3743 2397.92,3743 505,3830 565,3830 600,3935 520,3936.26
  other v2: 3180,2295 3220,2295 3260,2295 3695,2300 3735,2300 3775,2300 3815,2300 3180,2335 3695,2340 3735,2340 3775,2340 3815,2340 3180,2375 3695,2380 3735,2380 3775,2380 3815,2380 3695,2420 3735,2420 3775,2420 3815,2420 3695,2460 3735,2460 3775,2460 3815,2460 3695,2500 3735,2500 3775,2500 3815,2500 3695,2550 3735,2550 3775,2550 3815,2550 3695,2590 3735,2590 3775,2590 3815,2590 3695,2630 3735,2630 3775,2630 3815,2630 3695,2670 3735,2670 3775,2670 3815,2670 3180,2675 3695,2710 3735,2710 3775,2710 3815,2710 3180,2715 3695,2750 3735,2750 3775,2750 3815,2750 3180,2755 3220,2755 3260,2755
  other v3: 1755.48,913 1800.48,913 1780.48,938 1825.48,938 1755.48,963 1800.48,963 1780.48,988 1825.48,988 1755.48,1018 1800.48,1018 1755.48,2783 1800.48,2783 1780.48,2808 1825.48,2808 1755.48,2833 1800.48,2833 1780.48,2858 1825.48,2858 1755.48,2888 1800.48,2888
  other v4: 540,3670.79 498.66,3720 540,3720 581.34,3720 540,3769.21
MSEL1_P1: R13_P1.2 R21_P1.1 U1_P1.32 | length 412.4
  Top Layer w10: R13_P1.2@1510,3137.56 1540.39,3107.17 1540.27,3107.04 1540.27,3049.73 ; 1540.39,3049.61 1560,3030 1590,3030 1610,3010 1645,3010 1670,2985 1700,2985 1736.73,2948.27 U1_P1.32@1736.73,2929.49
  Top Layer w30: R13_P1.2@1510,3137.56 R21_P1.1@1510,3192.44
MSEL1_P2: R13_P2.2 R21_P2.1 U1_P2.32 | length 412.4
  Top Layer w10: R13_P2.2@1510,1267.56 1540.39,1237.17 1540.27,1237.04 1540.27,1179.73 ; 1540.39,1179.61 1560,1160 1590,1160 1610,1140 1645,1140 1670,1115 1700,1115 1736.73,1078.27 U1_P2.32@1736.73,1059.49
  Top Layer w30: R13_P2.2@1510,1267.56 R21_P2.1@1510,1322.44
MSEL2_P1: R10_P1.2 R18_P1.1 U1_P1.29 | length 317
  Top Layer w10: R10_P1.2@1690,3137.56 1692.56,3135 1710,3135 1720,3125 1720,3056.67 1795.79,2980.88 U1_P1.29@1795.79,2929.49
  Top Layer w30: R10_P1.2@1690,3137.56 R18_P1.1@1690,3192.44
MSEL2_P2: R10_P2.2 R18_P2.1 U1_P2.29 | length 317
  Top Layer w10: R10_P2.2@1690,1267.56 1692.56,1265 1710,1265 1720,1255 1720,1186.67 1795.79,1110.88 U1_P2.29@1795.79,1059.49
  Top Layer w30: R10_P2.2@1690,1267.56 R18_P2.1@1690,1322.44
NetC12_P1_2: C12_P1.2 R6_P1.2
NetC12_P2_2: C12_P2.2 R6_P2.2
NetC13_P1_1: C13_P1.1 D1_P1.1 R4_P1.1 | length 119.6
  Top Layer w10: C13_P1.1@1842.11,2523.2 C13_P1.1@1844.67,2525.76
  Top Layer w20: C13_P1.1@1837.44,2520 1840,2522.56 R4_P1.1@1840,2577.44
  Top Layer w30: C13_P1.1@1837.44,2520 1837.44,2492.56 v1(1840,2490)
  Bottom Layer w20: D1_P1.1@1815,2493.35 1818.35,2490 v1(1840,2490)
NetC13_P2_1: C13_P2.1 D1_P2.1 R4_P2.1 | length 120
  Top Layer w10: C13_P2.1@1842.11,653.2 C13_P2.1@1844.67,655.76
  Top Layer w20: C13_P2.1@1837.44,650 ccw(c1837.44,652.56) 1840,652.56 R4_P2.1@1840,707.44
  Top Layer w30: C13_P2.1@1837.44,650 1837.44,622.56 v1(1840,620)
  Bottom Layer w20: D1_P2.1@1815,623.35 1818.35,620 v1(1840,620)
NetC17_P1_1: C17_P1.1 R32.1 U1_P1.33 | length 181.3
  Top Layer w10: C17_P1.1@1625,2972.56 1693.66,2903.9 U1_P1.33@1711.14,2903.9
  Top Layer w20: R32.1@1567.56,2995 1580,2995 1602.44,2972.56 C17_P1.1@1625,2972.56
NetC17_P1_2: C17_P1.2 R8_P1.2 R33.1 U1_P1.34 | length 154.9
  Top Layer w10: C17_P1.2@1625,2917.44 1658.23,2884.21 U1_P1.34@1711.14,2884.21
  Top Layer w30: R8_P1.2@1567.56,2885 R33.1@1567.56,2940
NetC17_P2_1: C17_P2.1 R37.1 U1_P2.33 | length 183.4
  Top Layer w10: C17_P2.1@1625,1102.56 1627.44,1102.56 1696.1,1033.9 U1_P2.33@1711.14,1033.9
  Top Layer w20: R37.1@1567.56,1130 1585,1130 1612.44,1102.56 C17_P2.1@1625,1102.56
NetC17_P2_2: C17_P2.2 R8_P2.2 R39.1 U1_P2.34 | length 154.9
  Top Layer w10: C17_P2.2@1625,1047.44 1658.23,1014.21 U1_P2.34@1711.14,1014.21
  Top Layer w30: R8_P2.2@1567.56,1015 R39.1@1567.56,1070
NetC20_P1_1: C20_P1.1 JP2_P1.3 R9_P1.1 R14_P1.1 | length 218.1
  Bottom Layer w30: JP2_P1.3@1365,3185 1372.44,3192.44 R14_P1.1@1470,3192.44 C20_P1.1@1525,3192.44 R9_P1.1@1580,3192.44
NetC20_P2_1: C20_P2.1 JP2_P2.3 R9_P2.1 R14_P2.1 | length 218.1
  Bottom Layer w30: JP2_P2.3@1365,1315 1372.44,1322.44 R14_P2.1@1470,1322.44 C20_P2.1@1525,1322.44 R9_P2.1@1580,1322.44
NetC21_P1_1: C21_P1.1 R15_P1.2 U1_P1.35 | length 157.9
  Top Layer w10: R15_P1.2@1567.56,2830 1582.47,2830 1608.67,2856.2 1616.99,2864.53 U1_P1.35@1711.14,2864.53
NetC21_P2_1: C21_P2.1 R15_P2.2 U1_P2.35 | length 157.9
  Top Layer w10: R15_P2.2@1567.56,960 1582.47,960 1608.67,986.2 1616.99,994.53 U1_P2.35@1711.14,994.53
NetC24_1: C24.1 U2.4 | length 290
  Top Layer w10: U2.4@465.2,3710.16 410.16,3710.16 400,3700 400,3570 437.56,3532.44 C24.1@475,3532.44
NetD1_P1_2: D1_P1.2 R1_P1.2 | length 52.9
  Bottom Layer w20: D1_P1.2@1815,2541.65 1815,2587.44 R1_P1.2@1820,2592.44
NetD1_P2_2: D1_P2.2 R1_P2.2 | length 52.9
  Bottom Layer w20: D1_P2.2@1815,671.65 1815,717.44 R1_P2.2@1820,722.44
NetJ2_5: J2.5 R28.1 | length 761.3
  Top Layer w30: J2.5@175,625 100,550 100,350 300,150 R28.1@472.44,150
NetJP3_1: JP3.1 U2.5 | length 482.4
  Top Layer w10: v1(425,3685) 430.47,3690.47 U2.5@465.2,3690.47
  Signal Layer 2 w30: v1(425,3685) 495,3615 585,3615 720,3750 JP3.1@780,3750
NetLED1_2: LED1.2 R28.2 | length 65.9
  Top Layer w30: R28.2@527.56,150 LED1.2@593.5,150
NetR4_P1_2: R4_P1.2 U1_P1.7 | length 114.1
  Top Layer w10: R4_P1.2@1840,2632.56 1840,2665 1854.84,2679.84 U1_P1.7@1854.84,2740.51
NetR4_P2_2: R4_P2.2 U1_P2.7 | length 114.1
  Top Layer w10: R4_P2.2@1840,762.56 1840,795 1854.84,809.84 U1_P2.7@1854.84,870.51
NetR5_P1_1: R5_P1.1 SMB1_P1.1 TP2_P1.1 | length 599.8
  Top Layer w20: SMB1_P1.1@1709.65,2185 TP2_P1.1@1830,2185 ; TP2_P1.1@1842.11,2197.11 TP2_P1.1@1830,2185 ; TP2_P1.1@1872.48,2185 TP2_P1.1@1870,2185 TP2_P1.1@1830,2185
  Bottom Layer w30: TP2_P1.1@1870,2185 1900,2215 R5_P1.1@1900,2592.44
NetR5_P2_1: R5_P2.1 SMB1_P2.1 TP2_P2.1 | length 599.8
  Top Layer w20: SMB1_P2.1@1709.65,315 TP2_P2.1@1830,315 ; TP2_P2.1@1842.11,327.11 TP2_P2.1@1830,315 ; TP2_P2.1@1872.48,315 TP2_P2.1@1870,315 TP2_P2.1@1830,315
  Bottom Layer w30: TP2_P2.1@1870,315 1900,345 R5_P2.1@1900,722.44
NetR15_P1_1: R15_P1.1 R15_P2.1 TP21.1 | length 4089.4
  Top Layer w30: v1(1485,960) R15_P2.1@1512.44,960 ; v1(1485,2830) R15_P1.1@1512.44,2830
  Signal Layer 2 w15: v1(1485,960) 1520,960 1600,1040 1600,1305 1415,1490 1155,1490 1060,1585 1060,1990 1390,2320 1390,2735 v1(1485,2830)
  Signal Layer 3 w15: TP21.1@125,3275 335,3275 560,3050 1196.93,3050 1416.93,2830 v1(1485,2830)
NetR16_P1_1: R16_P1.1 U1_P1.39 | length 177
  Top Layer w10: R16_P1.1@1567.56,2705 1614.92,2705 1695.71,2785.79 U1_P1.39@1711.14,2785.79
NetR16_P1_2: R16_P1.2 R16_P2.2 TP31.1 | length 2641.4
  Top Layer w30: TP31.1@1250,2825 1370,2705 v1(1485,2705) R16_P1.2@1512.44,2705 ; v1(1485,835) R16_P2.2@1512.44,835
  Signal Layer 4 w15: v1(1485,835) 1455,835 1140,1150 1140,1695 1640,2195 1640,2550 v1(1485,2705)
NetR16_P2_1: R16_P2.1 U1_P2.39 | length 177
  Top Layer w10: R16_P2.1@1567.56,835 1614.92,835 1695.71,915.79 U1_P2.39@1711.14,915.79
NetR17_P1_2: R17_P1.2 U1_P1.38 | length 162.4
  Top Layer w10: R17_P1.2@1567.56,2760 1644.47,2760 1689.94,2805.47 U1_P1.38@1711.14,2805.47
NetR17_P2_2: R17_P2.2 U1_P2.38 | length 162.4
  Top Layer w10: R17_P2.2@1567.56,890 1644.47,890 1689.94,935.47 U1_P2.38@1711.14,935.47
NetR22_P1_1: R22_P1.1 U1_P1.40 | length 191.7
  Top Layer w10: R22_P1.1@1567.56,2650 1588,2650 1704.1,2766.1 U1_P1.40@1711.14,2766.1
NetR22_P1_2: R22_P1.2 R22_P2.2 TP29.1 | length 2595
  Top Layer w30: TP29.1@1250,2625 1275,2650 v1(1485,2650) R22_P1.2@1512.44,2650 ; v1(1485,780) R22_P2.2@1512.44,780
  Signal Layer 4 w15: v1(1485,780) 1467,780 1110,1137 1110,1715 1610,2215 1610,2525 v1(1485,2650)
NetR22_P2_1: R22_P2.1 U1_P2.40 | length 191.7
  Top Layer w10: R22_P2.1@1567.56,780 1588,780 1704.1,896.1 U1_P2.40@1711.14,896.1
NetR23_P1_1: R23_P1.1 U1_P1.2 | length 315.6
  Top Layer w10: R23_P1.1@1567.56,2540 1595,2540 1630,2575 1630,2630 1686.2,2686.2 1721.67,2686.2 1756.42,2720.95 U1_P1.2@1756.42,2740.51
NetR23_P2_1: R23_P2.1 U1_P2.2 | length 312.7
  Top Layer w10: R23_P2.1@1567.56,670 1595,670 1630,705 1630,755 1691.2,816.2 1721.67,816.2 1756.42,850.95 U1_P2.2@1756.42,870.51
NetR25_P1_1: R25_P1.1 U1_P1.3 | length 376.1
  Top Layer w10: R25_P1.1@1567.56,2485 1595,2485 1655,2545 1655,2625 1698.2,2668.2 1729.13,2668.2 1776.1,2715.18 U1_P1.3@1776.1,2740.51
NetR25_P2_1: R25_P2.1 U1_P2.3 | length 375.8
  Top Layer w10: R25_P2.1@1567.56,615 1595,615 1655,675 1655,754.54 1698.66,798.2 1729.13,798.2 1776.1,845.18 U1_P2.3@1776.1,870.51
NetR27_P1_1: R27_P1.1 U1_P1.6 | length 204.5
  Top Layer w10: R27_P1.1@1770,2567.56 1777.56,2567.56 1805,2595 1805,2662 1835.16,2692.16 U1_P1.6@1835.16,2740.51 U1_P1.6@1835,2740.51
NetR27_P2_1: R27_P2.1 U1_P2.6 | length 204.5
  Top Layer w10: R27_P2.1@1770,697.56 1777.56,697.56 1805,725 1805,795 1835.16,825.16 U1_P2.6@1835.16,870.51 U1_P2.6@1835,870.51
NetR29_1: R29.1 R30.2 R31.2 U2.8 | length 326.6
  Top Layer w10: U2.8@614.8,3690.47 634.53,3690.47 650,3675 650,3645 623.2,3618.2 623.2,3535.65 620,3532.44
  Top Layer w30: R30.2@530,3532.44 R31.2@585,3532.44 620,3532.44 R29.1@660,3532.44
NetR29_2: R29.2 U2.9 | length 167.2
  Top Layer w10: U2.9@614.8,3710.16 644.84,3710.16 670,3685 670,3630 660,3620 R29.2@660,3587.56
NetR34_1: R34.1 TP14.1 | length 119
  Bottom Layer w30: TP14.1@3800,3200 3797.44,3202.56 cw(c3797.44,3197.56) 3802.44,3197.56 R34.1@3802.44,3090
NetR38_2: R38.2 TP28.1 | length 114
  Bottom Layer w30: TP28.1@3800,3425 3797.44,3427.56 cw(c3797.44,3422.56) 3802.44,3422.56 R38.2@3802.44,3320
PG_P1: R24_P1.2 R26_P1.2 TP5_P1.1 U1_P1.1 | length 941.6
  Top Layer w10: R24_P1.2@1567.56,2595 1693.56,2721 v1(1703,2721) 1728,2721 1736.73,2729.73 U1_P1.1@1736.73,2740.51
  Signal Layer 3 w20: TP5_P1.1@1250,2425 1525,2425 1600,2500 1600,2618 v1(1703,2721)
  Bottom Layer w20: R26_P1.2@1655,2752.56 1671.44,2752.56 v1(1703,2721)
PG_P2: R24_P2.2 R26_P2.2 TP5_P2.1 U1_P2.1 | length 960
  Top Layer w10: R24_P2.2@1567.56,725 1676.76,834.2 1714.21,834.2 1736.73,856.72 U1_P2.1@1736.73,870.51
  Signal Layer 3 w20: TP5_P2.1@1250,550 1545,550 1610,615 1610,758 v1(1703,851)
  Bottom Layer w20: R26_P2.2@1655,882.56 1671.44,882.56 v1(1703,851)
PG_Stack: R24_P1.1 R24_P2.1 | length 2383.5
  Top Layer w30: v1(1485,725) R24_P2.1@1512.44,725 ; v1(1485,2595) R24_P1.1@1512.44,2595
  Signal Layer 4 w15: v1(1485,725) 1460,725 1055,1130 1055,2030 1445,2420 1510,2420 1545,2455 1545,2535 v1(1485,2595)
PVIN_P1: C2_P1.1 C2_P2.1 C3_P1.1 C3_P2.1 C4_P1.1 C4_P2.1 C5_P1.2 C5_P2.2 C6_P1.2 C6_P2.2 C7_P1.2 C7_P2.2 C8_P1.2 C8_P2.2 C9_P1.2 C9_P2.2 C33.1 C34.1 JP4.1 R3_P1.2 R3_P2.2 R9_P1.2 R9_P2.2 T1.1 T1.2 TP1_P1.1 TP1_P2.1 TP12.1 U1_P1.21 U1_P1.22 U1_P1.23 U1_P1.24 U1_P1.25 U1_P2.21 U1_P2.22 U1_P2.23 U1_P2.24 U1_P2.25 | length 4341.8
  Signal Layer 5 w10: TP1_P2.1@1400,1650 1400,1660 1655,1915 2000,1915 2035,1880 2035,1140 v1(1980,1085) ; TP1_P1.1@1500,3875 1595,3780 2005,3780 2035,3750 2035,3010 v1(1980,2955)
  Bottom Layer w15: R9_P2.2@1580,1377.56 1580,1385 1505,1460 1505,1530 1535,1560 1695,1560 1872,1383 v1(1912.92,1383) ; R9_P1.2@1580,3247.56 1580,3255 1500,3335 1500,3395 1530,3425 1700,3425 1872,3253 v1(1912.92,3253)
  other v1: 1944.92,1123 1944.92,1178 1912.92,1243 1992.92,1243 1912.92,1273 1992.92,1273 1912.92,1303 1992.92,1303 1992.92,1383 1912.92,1413 1992.92,1413 1912.92,1443 1992.92,1443 1749.18,1653 1794.18,1653 1839.18,1653 1884.18,1653 1929.18,1653 1974.18,1653 1749.18,1683 1842.92,1683 1887.92,1683 1932.92,1683 1974.18,1683 1795,1685 1749.18,1738 1974.18,1738 1749.18,1773 1974.18,1773 1749.18,1833 1797.92,1833 1842.92,1833 1887.92,1833 1932.92,1833 1974.18,1833 1749.18,1863 1794.18,1863 1839.18,1863 1884.18,1863 1929.18,1863 1974.18,1863 125,2025 175,2025 225,2025 275,2025 325,2025 375,2025 575,2025 625,2025 675,2025 725,2025 775,2025 825,2025 125,2075 175,2075 325,2075 375,2075 575,2075 625,2075 775,2075 825,2075 125,2125 175,2125 325,2125 375,2125 575,2125 625,2125 775,2125 825,2125 125,2175 175,2175 325,2175 375,2175 575,2175 625,2175 775,2175 825,2175 125,2225 175,2225 325,2225 375,2225 575,2225 625,2225 775,2225 825,2225 125,2300 175,2300 225,2300 275,2300 325,2300 125,2348.62 175,2348.62 275,2348.62 225,2350 325,2350 275,2400 325,2400 275,2450 325,2450 125,2575 175,2575 225,2575 275,2575 325,2575 125,2625 175,2625 225,2625 275,2625 325,2625 275,2680 325,2680 275,2730 325,2730 325,2780 125,2781.38 175,2781.38 225,2781.38 275,2781.38 125,2830 175,2830 275,2830 325,2830 225,2831.38 1944.92,2993 1944.92,3048 1912.92,3113 1992.92,3113 1912.92,3143 1992.92,3143 1912.92,3173 1992.92,3173 1992.92,3253 1912.92,3283 1992.92,3283 1912.92,3313 1992.92,3313 1752.92,3523 1797.92,3523 1842.92,3523 1887.92,3523 1932.92,3523 1977.92,3523 1752.92,3553 1797.92,3553 1842.92,3553 1887.92,3553 1932.92,3553 1977.92,3553 1752.92,3608 1977.92,3608 1752.92,3643 1977.92,3643 1752.92,3703 1797.92,3703 1842.92,3703 1887.92,3703 1932.92,3703 1977.92,3703 1752.92,3733 1797.92,3733 1842.92,3733 1887.92,3733 1932.92,3733 1977.92,3733
SMBALT: J2.8 R27_P1.2 R27_P2.2 TP8.1 | length 5398.2
  Top Layer w30: J2.8@275,525 280,525 625,870 TP8.1@625,905 ; v1(1745,590) 1770,615 R27_P2.2@1770,642.44 ; v1(1745,2455) 1770,2480 R27_P1.2@1770,2512.44
  Signal Layer 4 w15: TP8.1@625,905 440,720 440,370 525,285 715,285 810,380 1535,380 v1(1745,590)
  Signal Layer 5 w15: v1(1745,590) 1655,590 1605,640 1605,1035 1735,1165 1735,1215 1460,1490 1200,1490 1155,1535 1155,1800 1745,2390 v1@1745,2450
SW_P1: C12_P1.1 C13_P1.2 L1.1 R5_P1.2 U1_P1.8 U1_P1.9 U1_P1.10 U1_P1.11 U1_P1.12
  other v1: 1900,2700 1925,2700
SW_P2: C12_P2.1 C13_P2.2 L2.1 R5_P2.2 U1_P2.8 U1_P2.9 U1_P2.10 U1_P2.11 U1_P2.12
  other v1: 1900,830 1925,830
VDD5_P1: C1_P1.2 C14_P1.2 C15_P1.2 C16_P1.2 JP1_P1.2 R1_P1.1 R7_P1.1 R26_P1.1 U1_P1.28 | length 1344.3
  Top Layer w10: v1(1790,3025) 1790,3015 1815.47,2989.53 U1_P1.28@1815.47,2929.49
  Top Layer w20: JP1_P1.2@1675,3365 1745,3295 1745,3080 1767.56,3057.44 1780,3057.44 1780,3035 v1(1790,3025)
  Bottom Layer w20: R7_P1.1@1655,2647.56 1602.44,2700.12 1602.44,2857.44 1717.56,2972.56 C14_P1.2@1745,2972.56 1745,3095 1715,3125 1715,3325 JP1_P1.2@1675,3365
VDD5_P2: C1_P2.2 C14_P2.2 C15_P2.2 C16_P2.2 JP1_P2.2 R1_P2.1 R7_P2.1 R26_P2.1 U1_P2.28 | length 1100
  Top Layer w10: v1(1790,1155) 1790,1145 1815.47,1119.53 U1_P2.28@1815.47,1059.49
  Top Layer w20: JP1_P2.2@1675,1495 1745,1425 1745,1200 v1(1790,1155)
  Bottom Layer w20: C14_P2.2@1745,1102.56 1717.56,1102.56 1602.44,987.44 1602.44,797.56 1620,780 ccw(c1622.44,780) 1622.44,777.56 R7_P2.1@1655,777.56 R1_P2.1@1820,777.56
